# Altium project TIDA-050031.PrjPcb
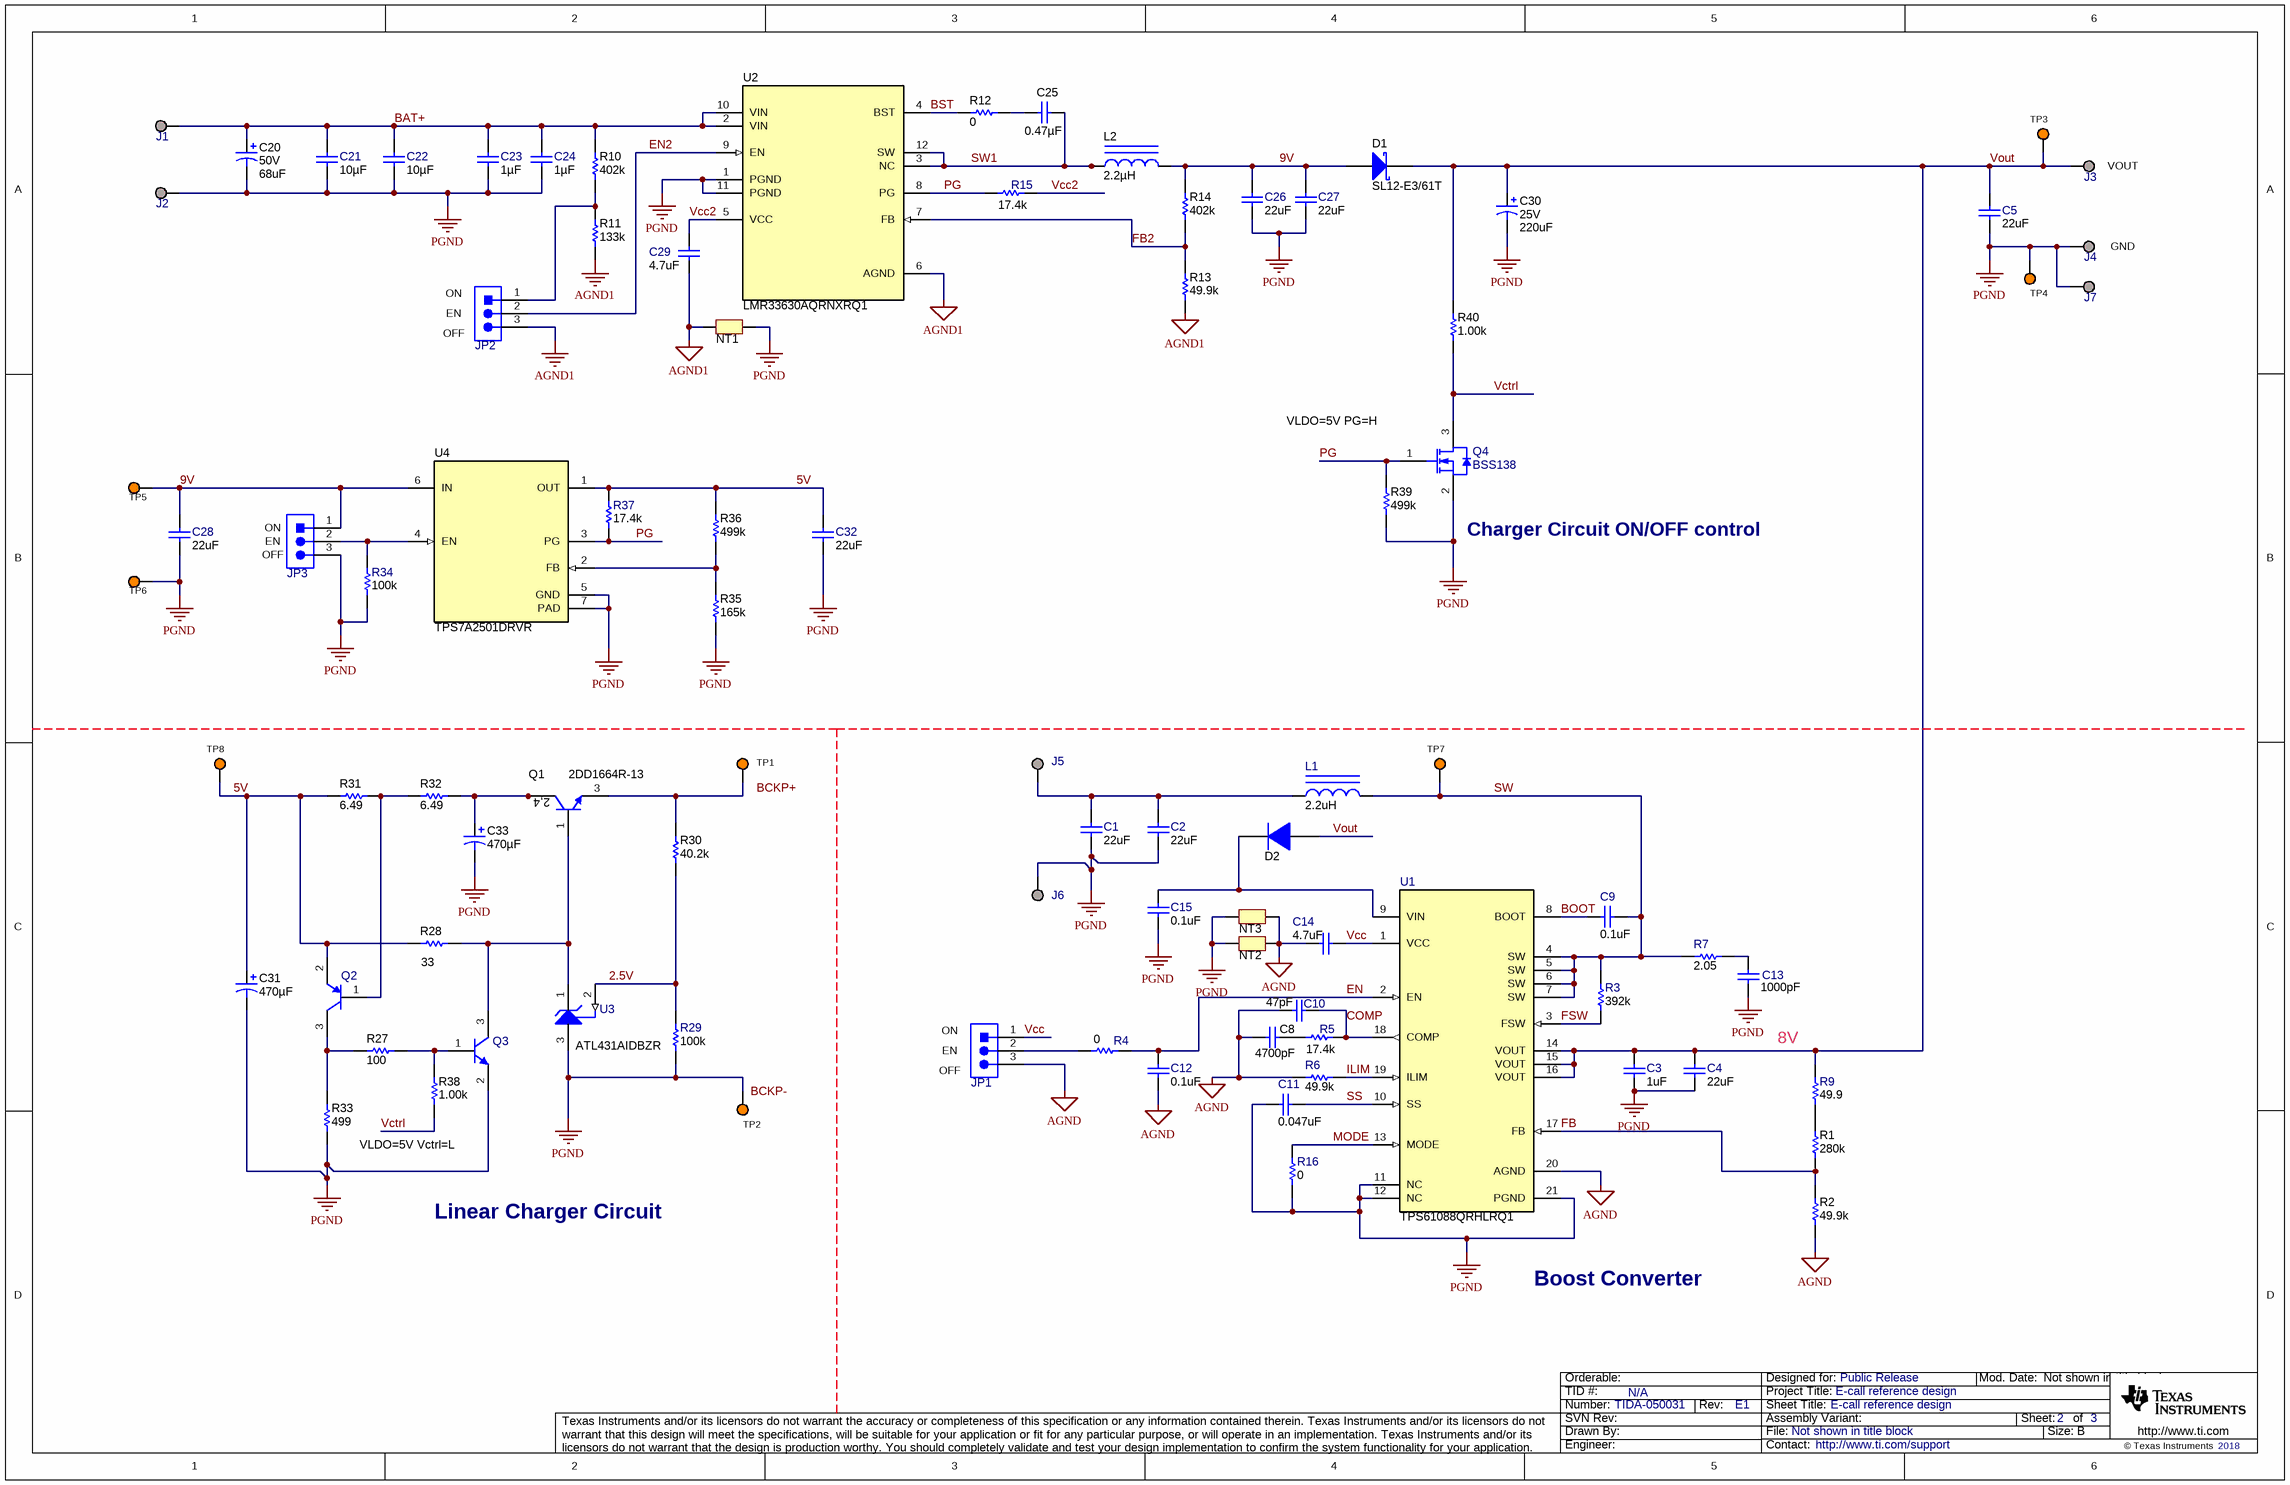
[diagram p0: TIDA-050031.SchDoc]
CopyrightYear: 2018; PCB_Layout: Helen; PCB_Rev: E1; PRJ_Customer: Public Release; PRJ_Number: TIDA-050031; PRJ_Title: E-call reference design; SCH_Rev: E1; TechSupport: http://www.ti.com/support; TID: N/A
2 sheets, 93 parts. Net scope: global (net labels, ports and power ports of the same name join across sheets).
Board file: TIDA-050031.PcbDoc
Sheets:
  TIDA-050031.SchDoc
  TIDA-050031_Hardware.SchDoc

## Sheet TIDA-050031.SchDoc: E-call reference design
size 431 x 279 mm; Date: Not shown in title block; ApprovedBy: Not shown in title block; CheckedBy: Not shown in title block; Author: Not shown in title block; CompanyName: Not shown in title block; Engineer: Not shown in title block; Organization: Not shown in title block; Address1: Not shown in title block; Address2: Not shown in title block; Address3: Not shown in title block; Address4: Not shown in title block; DocumentNumber: 1; Revision: Use project parameter SCH_Rev; SheetNumber: 2; SheetTotal: 3; PageSetup: Record=PageOptions¦CenterHorizontal=True¦CenterVertical=True¦PrintScale=1.00¦XCorrection=1.00¦YCorrection=1.00¦PrintKind=0¦BorderSize=5000000¦LeftOffset=0¦BottomOffset=0¦Orientation=2¦PaperLength=1000¦PaperWidth=1000¦Scale=100¦PaperSource=15¦PrintQuality=600¦MediaType=1¦DitherType=10¦PaperKind=Letter¦PrintScaleMode=1

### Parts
C1  ValueDisplayed: 22uF  [1206_180]  (hidden comment: Capacitor)
C2  ValueDisplayed: 22uF  [1206_180]  (hidden comment: Capacitor)
C3  ValueDisplayed: 1uF  [0603]  (hidden comment: Capacitor)
C4  ValueDisplayed: 22uF  [1210_270]  (hidden comment: Capacitor)
C5  ValueDisplayed: 22uF  [1210_270]  (hidden comment: Capacitor)
C8  ValueDisplayed: 4700pF  [0402]  (hidden comment: Capacitor)
C9  ValueDisplayed: 0.1uF  [0402]  (hidden comment: Capacitor)
C10  value 47pF  [0402]  (hidden comment: Capacitor)
C11  ValueDisplayed: 0.047uF  [0402]  (hidden comment: Capacitor)
C12  ValueDisplayed: 0.1uF  [0402]  (hidden comment: Capacitor)
C13  ValueDisplayed: 1000pF  [0603]  (hidden comment: Capacitor)
C14  ValueDisplayed: 4.7uF  [0603]  (hidden comment: Capacitor)
C15  ValueDisplayed: 0.1uF  [0402]  (hidden comment: Capacitor)
C20  VDC_V: 50V  ValueDisplayed: 68uF  [SM_RADIAL_8MM]  (hidden comment: EEHZA1H680P)
C21  ValueDisplayed: 10µF  [1206_190]  (hidden comment: CGA5L1X7R1H106K160AC)
C22  ValueDisplayed: 10µF  [1206_190]  (hidden comment: CGA5L1X7R1H106K160AC)
C23  ValueDisplayed: 1µF  [0603]  (hidden comment: C1608X5R1H105K080AB)
C24  ValueDisplayed: 1µF  [0603]  (hidden comment: C1608X5R1H105K080AB)
C25  ValueDisplayed: 0.47µF  [0603]  (hidden comment: C1608X5R1H474K080AB)
C26  ValueDisplayed: 22uF  [1210_270]  (hidden comment: Capacitor)
C27  ValueDisplayed: 22uF  [1210_270]  (hidden comment: Capacitor)
C28  ValueDisplayed: 22uF  [1206_180]  (hidden comment: Capacitor)
C29  ValueDisplayed: 4.7uF  [0603]  (hidden comment: Capacitor)
C30  VDC_V: 25V  ValueDisplayed: 220uF  [SM_RADIAL_8MM]  (hidden comment: EEHZA1E221P)
C31  ValueDisplayed: 470µF  [M_630x1120]  (hidden comment: ECA-0JM471B)
C32  ValueDisplayed: 22uF  [1206_180]  (hidden comment: Capacitor)
C33  ValueDisplayed: 470µF  [M_630x1120]  (hidden comment: ECA-0JM471B)
D1  SL12-E3/61T  [SMA]
D2  1N4148W-7-F  [SOD-123]  (value not drawn)
J1  Suggest using a net name here  [Keystone1502-2]  (value not drawn)
J2  Turret  [Keystone1502-2]  (value not drawn)
J3  Turret  [Keystone1502-2]  (value not drawn)
J4  Turret  [Keystone1502-2]  (value not drawn)
J5  Turret  [Keystone1502-2]  (value not drawn)
J6  Turret  [Keystone1502-2]  (value not drawn)
J7  Turret  [Keystone1502-2]  (value not drawn)
JP1  Header_3x1_Launchpad  [CONN_PEC03SAAN]  (value not drawn)
JP2  Header_3x1_Launchpad  [CONN_PEC03SAAN]  (value not drawn)
JP3  Header_3x1_Launchpad  [CONN_PEC03SAAN]  (value not drawn)
L1  ValueDisplayed: 2.2uH  [XAL6030]  (hidden comment: Inductor_Iron)
L2  ValueDisplayed: 2.2µH  [XAL4020]  (hidden comment: XAL4020-222MEB)
NT1  Net-Tie  [Net-Tie_10mil]  (value not drawn)  (net tie, no BOM)
NT2  Net-Tie  [Net-Tie_10mil]  (value not drawn)  (net tie, no BOM)
NT3  Net-Tie  [Net-Tie_10mil]  (value not drawn)  (net tie, no BOM)
Q1  2DD1664R-13  [SOT-89-3]
Q2  BC857C-7-F  [SOT-23]  (value not drawn)
Q3  BC847CLT1G  [SOT-23]  (value not drawn)
Q4  BSS138  [SOT-23]
R1  ValueDisplayed: 280k  [0402]  (hidden comment: CRCW0402280KFKED)
R2  ValueDisplayed: 49.9k  [0402]  (hidden comment: CRCW040249K9FKED)
R3  ValueDisplayed: 392k  [0402]  (hidden comment: Resistor)
R4  value 0  [0402]  (hidden comment: Resistor)
R5  value 17.4k  [0402]  (hidden comment: Resistor)
R6  ValueDisplayed: 49.9k  [0402]  (hidden comment: Resistor)
R7  ValueDisplayed: 2.05  [0603]  (hidden comment: Resistor)
R9  value 49.9  [0402]  (hidden comment: Resistor)
R10  ValueDisplayed: 402k  [0402]  (hidden comment: CRCW0402402KFKED)
R11  ValueDisplayed: 133k  [0402]  (hidden comment: CRCW0402133KFKED)
R12  ValueDisplayed: 0  [0402]  (hidden comment: RC0402JR-070RL)
R13  ValueDisplayed: 49.9k  [0402]  (hidden comment: CRCW040249K9FKED)
R14  ValueDisplayed: 402k  [0402]  (hidden comment: CRCW0402402KFKED)
R15  value 17.4k  [0402]  (hidden comment: Resistor)
R16  value 0  [0402]  (hidden comment: Resistor)
R27  ValueDisplayed: 100  [0603]  (hidden comment: CRCW0603100RFKEA)
R28  ValueDisplayed: 33  [1206]  (hidden comment: CRCW120633R0JNEA)
R29  ValueDisplayed: 100k  [0402]  (hidden comment: CRCW0402100KFKED)
R30  ValueDisplayed: 40.2k  [0402]  (hidden comment: CRCW040240K2FKED)
R31  ValueDisplayed: 6.49  [1206]  (hidden comment: RC1206FR-076R49L)
R32  ValueDisplayed: 6.49  [1206]  (hidden comment: RC1206FR-076R49L)
R33  ValueDisplayed: 499  [0603]  (hidden comment: CRCW0603499RFKEA)
R34  ValueDisplayed: 100k  [0402]  (hidden comment: CRCW0402100KFKED)
R35  ValueDisplayed: 165k  [0402]  (hidden comment: CRCW0402165KFKED)
R36  ValueDisplayed: 499k  [0402]  (hidden comment: CRCW0402499KFKED)
R37  value 17.4k  [0402]  (hidden comment: Resistor)
R38  ValueDisplayed: 1.00k  [0402]  (hidden comment: CRCW04021K00FKED)
R39  ValueDisplayed: 499k  [0402]  (hidden comment: CRCW0402499KFKED)
R40  ValueDisplayed: 1.00k  [0402]  (hidden comment: CRCW04021K00FKED)
TP1  5003  [Keystone5003]  (value not drawn)
TP2  5003  [Keystone5003]  (value not drawn)
TP3  5003  [Keystone5003]  (value not drawn)
TP4  5003  [Keystone5003]  (value not drawn)
TP5  5003  [Keystone5003]  (value not drawn)
TP6  5003  [Keystone5003]  (value not drawn)
TP7  5003  [Keystone5003]  (value not drawn)
TP8  5003  [Keystone5003]  (value not drawn)
U1  TPS61088QRHLRQ1  [RHL0020A]
U2  LMR33630AQRNXRQ1  [RNX0012B]
U3  ATL431AIDBZR  [DBZ0003A_N]
U4  TPS7A2501DRVR  [DRV0006A]

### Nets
AGND: C8.2 C10.2 C12.2 C14.1 JP1.3 NT2.2 NT3.2 R2.1 R6.1 U1.20(AGND)
AGND1: C29.1 JP2.3 NT1.1 R11.1 R13.1 U2.6(AGND)
PGND: C1.2 C2.2 C3.2 C4.2 C5.2 C11.1 C13.2 C15.2 C20.2(-) C21.2 C22.2 C23.2 C24.2 C26.2 C27.2 C28.2 C30.2(-) C31.2(-) C32.2 C33.2(-) J2.1 J4.1 J6.1 J7.1 JP3.3 NT1.2 NT2.1 NT3.1 Q3.2(E) Q4.2(S) R16.2 R29.1 R33.1 R34.1 R35.1 R39.1 TP2.1 TP4.1 TP6.1 U1.11(NC) U1.12(NC) U1.21(PGND) U2.1(PGND) U2.11(PGND) U3.3(ANODE) U4.5(GND) U4.7(PAD)
2.5V: R29.2 R30.1 U3.2(REF)
5V: C31.1(+) C32.1 Q2.2(E) R28.1 R31.1 R36.2 R37.1 TP8.1 U4.1(OUT)
9V: C26.1 C27.1 C28.1 D1.2(A) JP3.1 L2.2 R14.2 TP5.1 U4.6(IN)
BAT+: C20.1(+) C21.1 C22.1 C23.1 C24.1 J1.1 R10.2 U2.2(VIN) U2.10(VIN)
BOOT: C9.2 U1.8(BOOT)
BST: R12.1 U2.4(BST)
COMP: C10.1 R5.2 U1.18(COMP)
EN: C12.1 R4.1 U1.2(EN)
EN2: JP2.2 U2.9(EN)
FB: R1.1 R2.2 U1.17(FB)
FB2: R13.2 R14.1 U2.7(FB)
FSW: R3.1 U1.3(FSW)
ILIM: R6.2 U1.19(ILIM)
MODE: R16.1 U1.13(MODE)
PG: Q4.1(G) R15.1 R37.2 R39.2 U2.8(PG) U4.3(PG)
SS: C11.2 U1.10(SS)
SW: C9.1 L1.2 R3.2 R7.1 TP7.1 U1.4(SW) U1.5(SW) U1.6(SW) U1.7(SW)
SW1: C25.1 L2.1 U2.3(NC) U2.12(SW)
Vcc: C14.2 JP1.1 U1.1(VCC)
Vcc2: C29.2 R15.2 U2.5(VCC)
Vctrl: Q4.3(D) R38.1 R40.1
Vout: C3.1 C4.1 C5.1 C30.1(+) D1.1(K) D2.2(A) J3.1 R9.2 R40.2 TP3.1 U1.14(VOUT) U1.15(VOUT) U1.16(VOUT)
NetC1_1: C1.1 C2.1 J5.1 L1.1
NetC8_1: C8.1 R5.1
NetC13_1: C13.1 R7.2
NetC15_1: C15.1 D2.1(K) U1.9(VIN)
NetC25_2: C25.2 R12.2
NetC33_1: C33.1(+) Q1.2(C) Q1.4(C) R32.2
NetJP1_2: JP1.2 R4.2
NetJP2_1: JP2.1 R10.1 R11.2
NetJP3_2: JP3.2 R34.2 U4.4(EN)
NetQ1_1: Q1.1(B) Q3.3(C) R28.2 U3.1(CATHODE)
NetQ1_3: Q1.3(E) R30.2 TP1.1
NetQ2_1: Q2.1(B) R31.2 R32.1
NetQ2_3: Q2.3(C) R27.1 R33.2
NetQ3_1: Q3.1(B) R27.2 R38.2
NetR1_2: R1.2 R9.1
NetR35_2: R35.2 R36.1 U4.2(FB)

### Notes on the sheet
- (near J3) VOUT
- (near JP2) ON
- GND
- (near JP2) OFF
- (near JP2) EN
- VLDO=5V PG=H
- (near JP3) EN
- (near JP3) OFF
- (near JP3) ON
- (near Q4) Charger Circuit ON/OFF control
- (near JP1) ON
- 8V
- (near TP2) BCKP-
- (near JP1) OFF
- (near JP1) EN
- VLDO=5V Vctrl=L
- Linear Charger Circuit
- Boost Converter
- Labels drawn without touching a wire or pin: BCKP+

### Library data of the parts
C1 C2 C28 C32 = CMP-0008946-2: CAP, CERM, 22 uF, 16 V, +/- 10%, X5R, 1206; PartNumber: GRM31CR61C226KE15L; Manufacturer: MuRata; Polarized: N; Value: 22uF; U/M: EA; Cap_F: 22µF; Value1: Unknown; VDC_V: 16V; TaMin_C: -55°C; TaMax_C: 85°C; Cap_Case: 1206; SizeArea_mm2: 5.12; SizeAreaWB_mm2: 10.92; SizeX_mm: 3.2; SizeY_mm: 1.6; SizeZ_mm: 1.8; AEC Category: Q200
C3 = CMP-0007405-4: CAP, CERM, 1 uF, 25 V, +/- 10%, X7R, 0603; PartNumber: GRM188R71E105KA12D; Manufacturer: MuRata; Polarized: N; Value: 1uF; U/M: EA; Cap_F: 1µF; Value1: Unknown; VDC_V: 25V; TaMin_C: -55°C; TaMax_C: 125°C; AEC Category: Q200; SizeArea_mm2: 1.28; SizeAreaWB_mm2: 4.68; SizeX_mm: 1.6; SizeY_mm: 0.8; SizeZ_mm: 1
C4 C5 C26 C27 = CMP-0009224-2: CAP, CERM, 22 uF, 25 V, +/- 10%, X7R, 1210; PartNumber: GRM32ER71E226KE15L; Manufacturer: MuRata; Polarized: N; Value: 22uF; U/M: EA; Cap_F: 22µF; Value1: Unknown; VDC_V: 25V; TaMin_C: -55°C; TaMax_C: 125°C; Cap_Case: 1210; SizeArea_mm2: 8; SizeAreaWB_mm2: 14.7; SizeX_mm: 3.2; SizeY_mm: 2.5; SizeZ_mm: 2.7; AEC Category: Q200
C8 = CMP-0006616-2: CAP, CERM, 4700 pF, 50 V, +/- 10%, X5R, 0402; PartNumber: GRM155R61H472KA01D; Manufacturer: MuRata; Polarized: N; Value: 4700pF; U/M: EA; Cap_F: 4.7nF; Value1: Unknown; VDC_V: 50V; TaMin_C: -55°C; TaMax_C: 85°C; AEC Category: Q200; SizeArea_mm2: 0.5; SizeAreaWB_mm2: 3; SizeX_mm: 1; SizeZ_mm: 0.6
C9 C12 C15 = CMP-0006591-2: CAP, CERM, 0.1 uF, 16 V, +/- 10%, X5R, 0402; PartNumber: GRM155R61C104KA88D; Manufacturer: MuRata; Polarized: N; Value: 0.1uF; U/M: EA; Cap_F: 100nF; Value1: Unknown; VDC_V: 16V; TaMin_C: -55°C; TaMax_C: 85°C; AEC Category: Q200; SizeArea_mm2: 0.5; SizeAreaWB_mm2: 3; SizeX_mm: 1; SizeZ_mm: 0.6
C10 = CMP-0006467-2: CAP, CERM, 47 pF, 50 V, +/- 1%, C0G/NP0, 0402; PartNumber: GRM1555C1H470FA01D; Manufacturer: MuRata; Polarized: N; U/M: EA; Value1: Unknown; VDC_V: 50V; TaMin_C: -55°C; TaMax_C: 125°C; AEC Category: Q200; SizeArea_mm2: 0.5; SizeAreaWB_mm2: 3; SizeX_mm: 1; SizeZ_mm: 0.6
C11 = CMP-0006653-2: CAP, CERM, 0.047 uF, 16 V, +/- 10%, X7R, 0402; PartNumber: GRM155R71C473KA01D; Manufacturer: MuRata; Polarized: N; U/M: EA; Cap_F: 47nF; Value1: Unknown; VDC_V: 16V; TaMin_C: -55°C; TaMax_C: 125°C; AEC Category: Q200; SizeArea_mm2: 0.5; SizeAreaWB_mm2: 3; SizeX_mm: 1; SizeZ_mm: 0.6
C13 = CMP-0007467-4: CAP, CERM, 1000 pF, 100 V, +/- 10%, X7R, 0603; PartNumber: GRM188R72A102KA01D; Manufacturer: MuRata; Polarized: N; Value: 1000pF; U/M: EA; Cap_F: 1nF; Value1: Unknown; VDC_V: 100V; TaMin_C: -55°C; TaMax_C: 125°C; AEC Category: Q200; SizeArea_mm2: 1.28; SizeAreaWB_mm2: 4.68; SizeX_mm: 1.6; SizeY_mm: 0.8; SizeZ_mm: 1
C14 C29 = CMP-0006816-5: CAP, CERM, 4.7 uF, 10 V, +/- 10%, X5R, 0603; PartNumber: 0603ZD475KAT2A; Manufacturer: AVX; Polarized: N; Value: 4.7uF; U/M: EA; Cap_F: 4.7µF; Value1: Unknown; VDC_V: 10V; TaMin_C: -55°C; TaMax_C: 85°C; AEC Category: Q200; SizeArea_mm2: 1.28; SizeAreaWB_mm2: 4.68; SizeX_mm: 1.6; SizeY_mm: 0.8; SizeZ_mm: 1
C20 = CMP-0012579-3: CAP, Polymer Hybrid, 68 uF, 50 V, +/- 20%, 30 ohm, 8x10 SMD; Manufacturer: Panasonic; TaMin_C: -55°C; ESR_ohm: 30; Polarized: Y; SizeAreaWB_mm2: 113.3; Value1: 30 ohm; Value: 68uF; TaMax_C: 105°C; SizeZ_mm: 10.2; SizeX_mm: 9; SizeY_mm: 8.3; SizeArea_mm2: 74.7; CompType: Capacitor; Cap_F: 68µF; IRMS_A: 1.8A; AEC Category: Q200
C21 C22 = CMP-0085950-1: CAP, CERM, 10 µF, 50 V,+/- 10%, X7R, AEC-Q200 Grade 1, 1206; Manufacturer: TDK; SizeZ_mm: 1.9; Value: 10uF; Value2: 50V; Cap_Case: 1206; AEC Grade: 1; TaMin_C: -55°C; U/M: EA; CompType: Capacitor; SizeArea_mm2: 5.12; TaMax_C: 125°C; AEC Qualified: Y; AEC Category: Q200; SizeX_mm: 3.2; SizeY_mm: 1.6; Polarized: N; SizeAreaWB_mm2: 10.92
C23 C24 = C1608X5R1H105K080AB: CAP, CERM, 1 µF, 50 V,+/- 10%, X5R, 0603; Manufacturer: TDK; Polarized: N; CompType: Capacitor; Value: 1uF; U/M: EA; Cap_F: 0.000001; Tolerance_%: 10; ESR_ohm: 0.005522; Value1: 0.005522 ohm; VDC_V: 50; Value2: 50V; IRMS_A: 2.21617; TaMin_C: -55; TaMax_C: 85; SizeArea_mm2: 1.28; SizeAreaWB_mm2: 4.68; SizeX_mm: 1.6; SizeY_mm: 0.8; SizeZ_mm: 1; AEC Category: Q200; Green_Lifecycle: Active; Green_REACh: Passed
C25 = C1608X5R1H474K080AB: CAP, CERM, 0.47 µF, 50 V,+/- 10%, X5R, 0603; Manufacturer: TDK; Polarized: N; CompType: Capacitor; Value: 0.47uF; U/M: EA; Cap_F: 0.00000047; Tolerance_%: 10; ESR_ohm: 0.010974; Value1: 0.010974 ohm; VDC_V: 50; Value2: 50V; IRMS_A: 1.57483; TaMin_C: -55; TaMax_C: 85; SizeArea_mm2: 1.28; SizeAreaWB_mm2: 4.68; SizeX_mm: 1.6; SizeY_mm: 0.8; SizeZ_mm: 1; AEC Category: Q200
C30 = CMP-0012571-3: CAP, Polymer Hybrid, 220 uF, 25 V, +/- 20%, 27 ohm, 8x10 SMD; Manufacturer: Panasonic; TaMin_C: -55°C; ESR_ohm: 27; Polarized: Y; SizeAreaWB_mm2: 113.3; Value1: 27 ohm; Value: 220uF; TaMax_C: 105°C; SizeZ_mm: 10.2; SizeX_mm: 9; SizeY_mm: 8.3; SizeArea_mm2: 74.7; CompType: Capacitor; Cap_F: 220µF; IRMS_A: 2.3A; AEC Category: Q200
C31 C33 = ECA-0JM471B: CAP, AL, 470 µF, 6.3 V, +/- 20%, TH; Manufacturer: Panasonic; Polarized: Y; CompType: Capacitor; Value: 470uF; U/M: EA; Cap_F: 0.00047; Tolerance_%: 20; VDC_V: 6.3; Value2: 6.3V; IRMS_A: 0.38; TaMin_C: -40; TaMax_C: 85; Cap_Case: 6.3x11.2mm; SizeAreaWB_mm2: 68.89; SizeArea_mm2: 39.69; SizeZ_mm: 12.2; AEC Category: Q200; AEC Qualified: N
D1 = SL12-E3/61T: Diode, Schottky, 20 V, 1.5 A, SMA; Manufacturer: Vishay-Semiconductor; U/M: EA; Vf_V: 0.445; Value: 20V; Value1: 1.5A; Value2: 0.445V; Io_A: 1.5; Vr_V: 20; TJmax_C: 125; RJC_CperW: 28; SizeAreaWB_mm2: 37.3428; SizeArea_mm2: 16.3228; SizeX_mm: 5.59; SizeY_mm: 2.92; SizeZ_mm: 2.87; AEC Category: Q101; Green_Lifecycle: Not Set; Green_REACh: Incomplete
D2 = 1N4148W-7-F: Diode, Ultrafast, 100 V, 0.15 A, SOD-123; Manufacturer: Diodes Inc.; U/M: EA; Vf_V: 1.25; Value: 100V; Value1: 0.15A; Value2: 1.25V; Io_A: 0.15; Vr_V: 100; TJmax_C: 150; SizeAreaWB_mm2: 13.095; SizeArea_mm2: 6.545; SizeX_mm: 3.85; SizeY_mm: 1.7; SizeZ_mm: 1.35; AEC Category: Q101; Green_Lifecycle: Active; Green_REACh: Passed
J1 = 1502-2: Terminal, Turret, TH, Double; Manufacturer: Keystone; CompType: Turret Terminal; U/M: EA
J2-J7 = CMP-0055113-1: Terminal, Turret, TH, Double; PartNumber: 1502-2; Manufacturer: Keystone; CompType: Turret Terminal; CNHeader: FALSE; Green_Lifecycle: Active; Green_REACh: Passed
JP1-JP3 = CMP-0002338-1: Header, 100mil, 3x1, Tin, TH; PartNumber: PEC03SAAN; Manufacturer: Sullins Connector Solutions; Pitch_mm: 2.54; Gender: Male; Shrouded: N; Row_Count: 1; Current_A: 3A; Voltage_V: 1.8kV; Cert_UL: Y; Green_Lifecycle: Not Set; Green_REACh: Incomplete; CNHeader: TRUE; CT: FALSE
L1 = CMP-0061015-1: Inductor, Shielded, Composite, 2.2 uH, 12.7 A, 0.012 ohm, SMD; PartNumber: XAL6030-222MEB; Manufacturer: Coilcraft; Value: 2.2uH; Ind_H: 2.2µH; Imax_A: 12.7A; Irms: 12.7A @ 40C rise; Isat: 15.9A @ 30% inductance drop; DCR_ohm: 0.012; SizeAreaWB_mm2: 71.5616; SizeArea_mm2: 41.7216; SizeX_mm: 6.36; SizeY_mm: 6.56; SizeZ_mm: 3.1; AEC Category: Q200; Green_Lifecycle: Not Set; Green_REACh: Incomplete
L2 = XAL4020-222MEB: Inductor, Shielded, Composite, 2.2 µH, 5.5 A, 0.04 ohm, SMD; Manufacturer: Coilcraft; Value: 2.2uH; Ind_H: 2.2E-6; Imax_A: 5.5; Irms: 5.5A @ 40C rise; Isat: 5.62A @ 30% inductance drop; DCR_ohm: 0.04; Value2: 5.5A; SizeAreaWB_mm2: 28.09; SizeArea_mm2: 18.49; SizeX_mm: 4.3; SizeZ_mm: 2.1; AEC Category: Q200; Green_Lifecycle: Not Set; Green_REACh: Incomplete
NT1-NT3 = CMP-0078142-1: Single point connection between nets.
Q1 = 2DD1664R-13, Diodes Inc.: Transistor, NPN, 32 V, 1 A, SOT-89; SymbolCreator: a0412235; PNP: 0; NPN: 1; Vceo_V: 32; Vcesat1_V: 0.4; Value: 32 V; Value1: 1 A; HfeMax: 390; TaMin_C: -55; TaMax_C: 150; SizeAreaWB_mm2: 28.05; SizeArea_mm2: 18.45; SizeX_mm: 4.1; SizeY_mm: 4.5; SizeZ_mm: 1.5; CompType: BJT; U/M: EA; AEC Category: Q101
Q2 = BC857C-7-F, Diodes Inc.: Transistor, PNP, 45 V, 0.1 A, SOT-23; CompType: BJT; PNP: 1; NPN: 0; Vceo_V: 45; Vcesat1_V: 0.075; Value: 45 V; IcRated_A: 0.1; Value1: 0.1 A; HfeMax: 600; TaMin_C: -65; TaMax_C: 150; SizeAreaWB_mm2: 14; SizeArea_mm2: 7.5; SizeX_mm: 2.5; SizeY_mm: 3; SizeZ_mm: 1.1; U/M: EA; AEC Category: Q101
Q3 = BC847CLT1G, ON Semiconductor: Transistor, NPN, 45 V, 0.1 A, SOT-23; CompType: BJT; PNP: 0; NPN: 1; Vceo_V: 45; Vcesat1_V: 0.7; Value: 45 V; IcRated_A: 0.1; Value1: 0.1 A; HfeMax: 800; TaMin_C: -55; TaMax_C: 150; SizeAreaWB_mm2: 14; SizeArea_mm2: 7.5; SizeX_mm: 2.5; SizeY_mm: 3; SizeZ_mm: 1.1; U/M: EA; AEC Category: Q101; Green_Lifecycle: Active; Green_REACh: Passed
Q4 = BSS138: MOSFET, N-CH, 50 V, 0.22 A, SOT-23; Manufacturer: Fairchild Semiconductor; Alternate Manufacturer: None; U/M: EA; ChType: N; Value: 50V; VdsMax_V: 50; Value1: 6 ohm; Rdson45_ohm: 6; Value2: 1.7 nC; QgTyp_nC: 1.7; Vgs_V: 20; IdsMax_A: 0.22
R1 = CRCW0402280KFKED: RES, 280 k, 1%, 0.063 W, 0402; Manufacturer: Vishay-Dale; CompType: Resistor; Value: 280k; Res_ohm: 280000; Tolerance_%: 1; Power_W: 0.063; Value2: 0.063W; VDC_V: 50; TempCo: 100 ppm/C; SizeArea_mm2: 0.5; SizeZ_mm: 0.6; EIA_Code: E96; U/M: EA; AEC Category: Q200
R2 R13 = CRCW040249K9FKED: RES, 49.9 k, 1%, 0.063 W, 0402; Manufacturer: Vishay-Dale; CompType: Resistor; Value: 49.9k; Res_ohm: 49900; Value_Code: 49k9; Tolerance_%: 1; Power_W: 0.063; Value2: 0.063W; VDC_V: 50; TempCo: 100 ppm/C; SizeArea_mm2: 0.5; SizeZ_mm: 0.6; EIA_Code: E96; U/M: EA; AEC Category: Q200; Green_Lifecycle: Active; Green_REACh: Passed
R3 = CMP-0026325-2: RES, 392 k, 1%, 0.063 W, AEC-Q200 Grade 0, 0402; PartNumber: CRCW0402392KFKED; Manufacturer: Vishay-Dale; Value: 392k; Power_W: 63mW; Value2: 0.063W; VDC_V: 50V; TempCo: 100 ppm/C; SizeArea_mm2: 0.5; SizeX_mm: 1; SizeZ_mm: 0.6; EIA_Code: E96; AEC Category: Q200; AEC Qualified: Y; AEC Grade: 0
R4 R16 = CMP-0027004-2: RES, 0, 5%, 0.063 W, 0402; PartNumber: RC0402JR-070RL; Manufacturer: Yageo America; Value_Code: 0000; Power_W: 63mW; Value2: 0.063W; VDC_V: 50V; TempCo: 200 ppm/C; EIA_Code: E24; U/M: EA; AEC Category: Q200; SizeArea_mm2: 0.5; SizeX_mm: 1; SizeZ_mm: 0.6
R5 R15 R37 = CMP-0026050-3: RES, 17.4 k, 1%, 0.063 W, AEC-Q200 Grade 0, 0402; PartNumber: CRCW040217K4FKED; Manufacturer: Vishay-Dale; Value_Code: 17k4; Power_W: 63mW; Value2: 0.063W; VDC_V: 50V; TempCo: 100 ppm/C; EIA_Code: E96; AEC Category: Q200; AEC Grade: 0; AEC Qualified: Y; SizeArea_mm2: 0.5; SizeX_mm: 1; SizeZ_mm: 0.6
R6 = CMP-0026403-2: RES, 49.9 k, 1%, 0.063 W, AEC-Q200 Grade 0, 0402; PartNumber: CRCW040249K9FKED; Manufacturer: Vishay-Dale; Value: 49.9k; Value_Code: 49k9; Power_W: 63mW; Value2: 0.063W; VDC_V: 50V; TempCo: 100 ppm/C; SizeArea_mm2: 0.5; SizeX_mm: 1; SizeZ_mm: 0.6; EIA_Code: E96; AEC Category: Q200; AEC Qualified: Y; AEC Grade: 0
R7 = CMP-0022303-4: RES, 2.05, 1%, 0.1 W, AEC-Q200 Grade 0, 0603; PartNumber: CRCW06032R05FKEA; Manufacturer: Vishay-Dale; Value: 2.05; Value_Code: 2R05; Power_W: 100mW; Value2: 0.1W; VDC_V: 75V; TempCo: 100 ppm/C; EIA_Code: E96; AEC Category: Q200; AEC Grade: 0; AEC Qualified: Y; SizeArea_mm2: 1.28; SizeX_mm: 1.6; SizeY_mm: 0.8; SizeZ_mm: 1
R9 = CMP-0026404-2: RES, 49.9, 1%, 0.063 W, AEC-Q200 Grade 0, 0402; PartNumber: CRCW040249R9FKED; Manufacturer: Vishay-Dale; Value_Code: 49R9; Power_W: 63mW; Value2: 0.063W; VDC_V: 50V; TempCo: 100 ppm/C; EIA_Code: E96; AEC Category: Q200; AEC Grade: 0; AEC Qualified: Y; SizeArea_mm2: 0.5; SizeX_mm: 1; SizeZ_mm: 0.6
R10 R14 = CRCW0402402KFKED: RES, 402 k, 1%, 0.063 W, 0402; Manufacturer: Vishay-Dale; CompType: Resistor; Value: 402k; Res_ohm: 402000; Tolerance_%: 1; Power_W: 0.063; Value2: 0.063W; VDC_V: 50; TempCo: 100 ppm/C; SizeArea_mm2: 0.5; SizeZ_mm: 0.6; EIA_Code: E96; U/M: EA; AEC Category: Q200
R11 = CRCW0402133KFKED: RES, 133 k, 1%, 0.063 W, 0402; Manufacturer: Vishay-Dale; CompType: Resistor; Value: 133k; Res_ohm: 133000; Tolerance_%: 1; Power_W: 0.063; Value2: 0.063W; VDC_V: 50; TempCo: 100 ppm/C; SizeArea_mm2: 0.5; SizeZ_mm: 0.6; EIA_Code: E96; U/M: EA; AEC Category: Q200; Green_Lifecycle: Active; Green_REACh: Passed
R12 = RC0402JR-070RL: RES, 0, 5%, 0.063 W, 0402; Manufacturer: Yageo America; CompType: Resistor; Value: 0; Value_Code: 0000; Tolerance_%: 5; Power_W: 0.063; Value2: 0.063W; VDC_V: 50; TempCo: 200 ppm/C; SizeArea_mm2: 0.5; SizeX_mm: 1; SizeZ_mm: 0.6; EIA_Code: E24; U/M: EA; AEC Category: Q200; Green_Lifecycle: Active; Green_REACh: Passed
R27 = CRCW0603100RFKEA: RES, 100, 1%, 0.1 W, 0603; Manufacturer: Vishay-Dale; CompType: Resistor; Value: 100; Value_Code: 100R; Tolerance_%: 1; Power_W: 0.1; Value2: 0.1W; VDC_V: 75; TempCo: 100 ppm/C; SizeArea_mm2: 1.28; SizeX_mm: 1.6; SizeY_mm: 0.8; EIA_Code: E96; U/M: EA; AEC Category: Q200; Green_Lifecycle: Active; Green_REACh: Passed
R28 = CRCW120633R0JNEA: RES, 33, 5%, 0.25 W, 1206; Manufacturer: Vishay-Dale; CompType: Resistor; Value: 33; Value_Code: 33R0; Tolerance_%: 5; Power_W: 0.25; Value2: 0.25W; VDC_V: 200; TempCo: 200 ppm/C; SizeArea_mm2: 5.12; SizeX_mm: 3.2; SizeY_mm: 1.6; SizeZ_mm: 1.35; EIA_Code: E24; U/M: EA; AEC Category: Q200; Green_Lifecycle: Active; Green_REACh: Passed
R29 R34 = CRCW0402100KFKED: RES, 100 k, 1%, 0.063 W, 0402; Manufacturer: Vishay-Dale; CompType: Resistor; Value: 100k; Res_ohm: 100000; Tolerance_%: 1; Power_W: 0.063; Value2: 0.063W; VDC_V: 50; TempCo: 100 ppm/C; SizeArea_mm2: 0.5; SizeZ_mm: 0.6; EIA_Code: E96; U/M: EA; AEC Category: Q200; Green_Lifecycle: Active; Green_REACh: Passed
R30 = CRCW040240K2FKED: RES, 40.2 k, 1%, 0.063 W, 0402; Manufacturer: Vishay-Dale; CompType: Resistor; Value: 40.2k; Res_ohm: 40200; Value_Code: 40k2; Tolerance_%: 1; Power_W: 0.063; Value2: 0.063W; VDC_V: 50; TempCo: 100 ppm/C; SizeArea_mm2: 0.5; SizeZ_mm: 0.6; EIA_Code: E96; U/M: EA; AEC Category: Q200; Green_Lifecycle: Active; Green_REACh: Passed
R31 R32 = RC1206FR-076R49L: RES, 6.49, 1%, 0.25 W, 1206; Manufacturer: Yageo America; CompType: Resistor; Value: 6.49; Value_Code: 6R49; Tolerance_%: 1; Power_W: 0.25; Value2: 0.25W; VDC_V: 200; TempCo: 200 ppm/C; SizeArea_mm2: 5.12; SizeX_mm: 3.2; SizeY_mm: 1.6; SizeZ_mm: 1.35; EIA_Code: E96; U/M: EA; AEC Category: Q200
R33 = CRCW0603499RFKEA: RES, 499, 1%, 0.1 W, 0603; Manufacturer: Vishay-Dale; CompType: Resistor; Value: 499; Value_Code: 499R; Tolerance_%: 1; Power_W: 0.1; Value2: 0.1W; VDC_V: 75; TempCo: 100 ppm/C; SizeArea_mm2: 1.28; SizeX_mm: 1.6; SizeY_mm: 0.8; EIA_Code: E96; U/M: EA; AEC Category: Q200; Green_Lifecycle: Active; Green_REACh: Passed
R35 = CRCW0402165KFKED: RES, 165 k, 1%, 0.063 W, 0402; Manufacturer: Vishay-Dale; CompType: Resistor; Value: 165k; Res_ohm: 165000; Tolerance_%: 1; Power_W: 0.063; Value2: 0.063W; VDC_V: 50; TempCo: 100 ppm/C; SizeArea_mm2: 0.5; SizeZ_mm: 0.6; EIA_Code: E96; U/M: EA; AEC Category: Q200
R36 R39 = CRCW0402499KFKED: RES, 499 k, 1%, 0.063 W, 0402; Manufacturer: Vishay-Dale; CompType: Resistor; Value: 499k; Res_ohm: 499000; Tolerance_%: 1; Power_W: 0.063; Value2: 0.063W; VDC_V: 50; TempCo: 100 ppm/C; SizeArea_mm2: 0.5; SizeZ_mm: 0.6; EIA_Code: E96; U/M: EA; AEC Category: Q200; Green_Lifecycle: Active; Green_REACh: Passed
R38 R40 = CRCW04021K00FKED: RES, 1.00 k, 1%, 0.063 W, 0402; Manufacturer: Vishay-Dale; CompType: Resistor; Value: 1.00k; Res_ohm: 1000; Value_Code: 1k00; Tolerance_%: 1; Power_W: 0.063; Value2: 0.063W; VDC_V: 50; TempCo: 100 ppm/C; SizeArea_mm2: 0.5; SizeZ_mm: 0.6; EIA_Code: E96; U/M: EA; AEC Category: Q200; Green_Lifecycle: Active; Green_REACh: Passed
TP1-TP8 = 5003: Test Point, Miniature, Orange, TH; Manufacturer: Keystone; CompType: Test Point Loop; U/M: EA
U1 = CMP-0082345-1: 10-A Fully-Integrated Synchronous Boost Converter, RHL0020A (VQFN-20); Alternate PartNumber: TPS61088QRHLTQ1; Alternate Manufacturer: Texas Instruments; SizeAreaWB_mm2: 24.75; Rating: Automotive; SizeZ_mm: 1; SizeX_mm: 4.5; SizeY_mm: 3.5; SizeArea_mm2: 15.75; CompType: IC; AEC Qualified: Y; AEC Category: Q200
U2 = CMP-0078601-4: Automotive 3.8-V to 36-V 3-A Synchronous Step-Down Voltage Regulator, RNX0012B (VQFN-HR-12); Alternate Manufacturer: Texas Instruments; Alternate PartNumber: LMR33630AQRNXTQ1; AEC Category: Q200; SizeZ_mm: 0.9; SizeAreaWB_mm2: 12.0; CompType: IC; SizeY_mm: 3.0; SizeX_mm: 2.0; SizeArea_mm2: 6.0; AEC Qualified: Y
U3 = ATL431AIDBZR: 2.5V Low Iq Adjustable Precision Shunt Regulator, DBZ0003A (SOT-23-3); Manufacturer: Texas Instruments; SymbolCreator: a0412235; SizeArea_mm2: 7.5; SizeAreaWB_mm2: 14; SizeX_mm: 2.5; SizeY_mm: 3; SizeZ_mm: 1.12; CompType: IC; U/M: EA
U4 = CMP-0078340-1: 300-mA, 18-V, Low IQ, Low Dropout Voltage Regulator with Power Good, DRV0006A (WSON-6); Manufacturer: Texas Instruments; SizeZ_mm: 0.8; SizeX_mm: 2; AEC Category: Q200; AEC Qualified: N; SizeArea_mm2: 4; CompType: IC; SizeAreaWB_mm2: 9

## Sheet TIDA-050031_Hardware.SchDoc
size 431 x 279 mm; Date: Not shown in title block; ApprovedBy: Not shown in title block; CheckedBy: Not shown in title block; Author: Not shown in title block; CompanyName: Not shown in title block; Engineer: Not shown in title block; Organization: Not shown in title block; Address1: Not shown in title block; Address2: Not shown in title block; Address3: Not shown in title block; Address4: Not shown in title block; DocumentNumber: 1; Revision: Use project parameter SCH_Rev; SheetNumber: 3; SheetTotal: 3; PageSetup: Record=PageOptions¦CenterHorizontal=True¦CenterVertical=True¦PrintScale=1.00¦XCorrection=1.00¦YCorrection=1.00¦PrintKind=0¦BorderSize=5000000¦LeftOffset=0¦BottomOffset=0¦Orientation=2¦PaperLength=1000¦PaperWidth=1000¦Scale=100¦PaperSource=15¦PrintQuality=600¦MediaType=1¦DitherType=10¦PaperKind=Letter¦PrintScaleMode=1
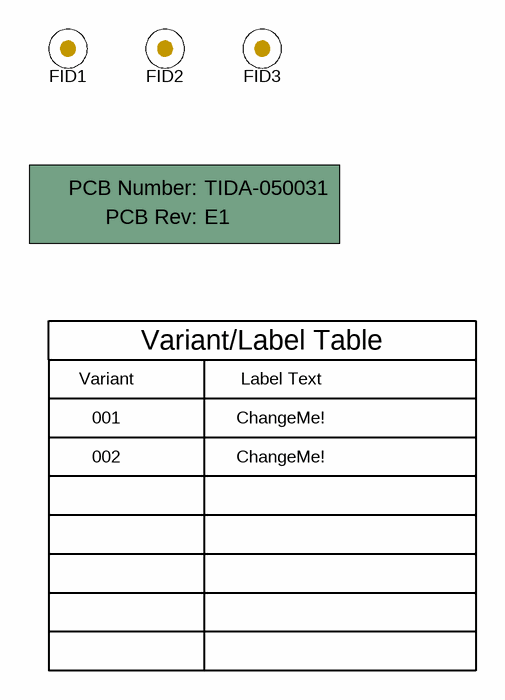
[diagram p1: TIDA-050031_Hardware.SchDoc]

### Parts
!PCB  Printed Circuit Board  (value not drawn)  (mechanical)
FID1  Fiducial  [Fiducial10-20]  (value not drawn)
FID2  Fiducial  [Fiducial10-20]  (value not drawn)
FID3  Fiducial  [Fiducial10-20]  (value not drawn)

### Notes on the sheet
- Variant/Label Table
- Variant
- 001
- 002
- Label Text
- ChangeMe!

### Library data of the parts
!PCB = CMP-0003618-2: Manufacturer: Any; PartNumber: TIDA-050031
FID1-FID3 = CMP-0077181-1: Fiducial mark.  There is nothing to buy or mount.

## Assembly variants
001: not fitted FID1 FID2 FID3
